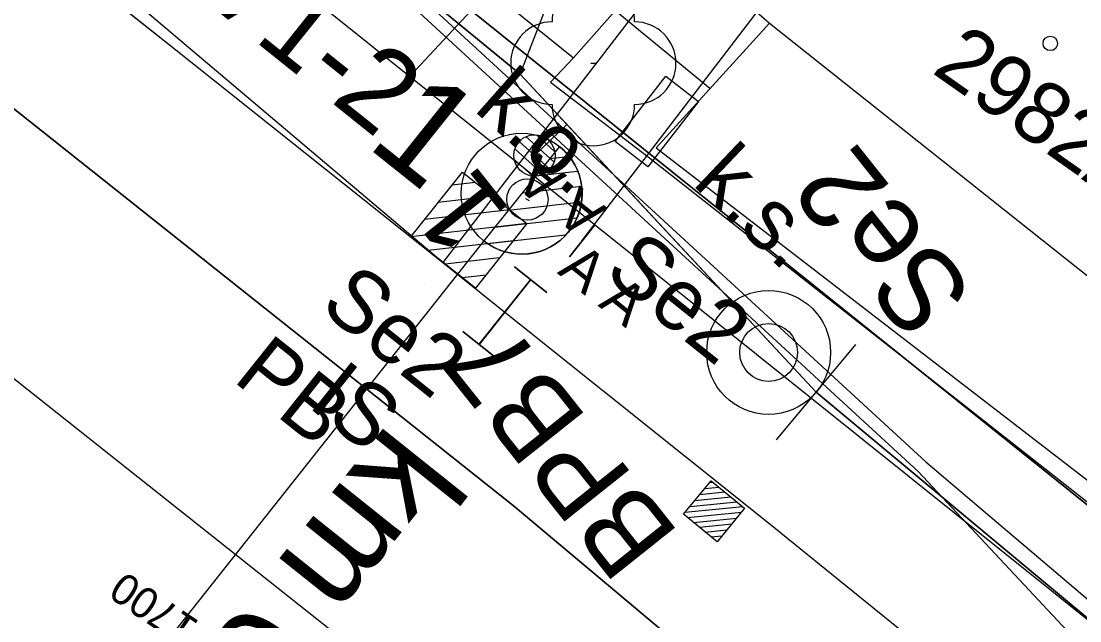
# Model space of a CAD drawing. Extents: x -620624 to -619936, y -1122925 to -1122325.
# Drawn here: x -620240.42 to -620214.78, y -1122741.3 to -1122726.78 of the extents above; entities that cross this region are included whole.
import ezdxf

# ---------------------------------------------------------------- set-up
doc = ezdxf.new("R2010")
doc.units = 0
for name, color, linetype in [('060603_ROZVODY_NN', 7, 'Continuous'), ('060604_ROZVODY_SEE', 7, 'Continuous'), ('CETIN', 7, 'Continuous'), ('POPIS KABELOVÉ TRASY', 7, 'Continuous'), ('PS 06-14-01_trasa_sdělovací_nové', 7, 'Continuous'), ('SEE', 7, 'Continuous'), ('SSZT', 7, 'Continuous'), ('SSZT-DK', 7, 'Continuous'), ('SSZT-TK', 7, 'Continuous'), ('Vrstva 1', 7, 'Continuous'), ('Vrstva 16', 7, 'Continuous'), ('Vrstva 2', 7, 'Continuous'), ('Vrstva 27', 7, 'Continuous'), ('Vrstva 3', 7, 'Continuous'), ('Vrstva 36', 7, 'Continuous'), ('Vrstva 50', 7, 'Continuous'), ('Vrstva 53', 7, 'Continuous'), ('Vrstva 55', 7, 'Continuous'), ('Vrstva 57', 7, 'Continuous'), ('Vrstva 6', 7, 'Continuous'), ('Vrstva 62', 7, 'Continuous'), ('ČD-T', 7, 'Continuous')]:
    doc.layers.add(name, color=color, linetype=linetype)

msp = doc.modelspace()

# ---------------------------------------------------------------- linework, layer by layer
at = {"layer": '060603_ROZVODY_NN'}
msp.add_lwpolyline([(-620240.174, -1122718.342), (-620228.339, -1122728.069), (-620221.166, -1122735.76), (-620213.633, -1122742.038), (-620205.954, -1122748.188), (-620177.512, -1122774.524), (-620185.522, -1122781.049), (-620181.59, -1122785.57), (-620173.131, -1122796.401), (-620158.909, -1122820.61), (-620151.64, -1122838.53), (-620148.846, -1122845.743), (-620146.967, -1122851.788), (-620142.651, -1122873.562), (-620132.315, -1122871.722), (-620130.544, -1122883.681), (-620130.195, -1122888.406), (-620130.037, -1122888.394)], dxfattribs=at)
at = {"layer": '060604_ROZVODY_SEE'}
msp.add_lwpolyline([(-620176.843, -1122775.143), (-620205.954, -1122748.188), (-620213.633, -1122742.038), (-620221.166, -1122735.76), (-620228.339, -1122728.069), (-620234.256, -1122723.205), (-620240.174, -1122718.342), (-620248.298, -1122711.665), (-620253.571, -1122707.331), (-620257.271, -1122704.364), (-620247.325, -1122692.032), (-620244.518, -1122694.296)], dxfattribs=at)
at = {"layer": 'CETIN'}
for points in [[(-620281.95, -1122736.09), (-620279.78, -1122731.91), (-620278.12, -1122730.04), (-620275.23, -1122726.8), (-620267.96, -1122716.51), (-620253.8, -1122706.08), (-620234.3, -1122721.82), (-620227.04, -1122727.67)], [(-620227.04, -1122727.67), (-620224.61, -1122724.91)], [(-620227.04, -1122727.67), (-620227.6, -1122728.26), (-620225.24, -1122730.07), (-620192.39, -1122755.87), (-620182.03, -1122766.47), (-620178.55, -1122770.03), (-620178.11, -1122770.48), (-620148.97, -1122814.05), (-620141.74, -1122827.78), (-620093.42, -1122851.53), (-620088.91, -1122854.99)]]:
    msp.add_lwpolyline(points, dxfattribs=at)
at = {"layer": 'POPIS KABELOVÉ TRASY'}
msp.add_lwpolyline([(-620228.339, -1122728.069), (-620218.049, -1122701.604), (-620224.371, -1122697.311)], dxfattribs=at)
at = {"layer": 'PS 06-14-01_trasa_sdělovací_nové'}
msp.add_lwpolyline([(-620232.134, -1122718.841), (-620235.045, -1122722.562), (-620243.025, -1122715.998), (-620248.321, -1122722.765), (-620228.504, -1122738.508), (-620211.634, -1122752.654), (-620198.933, -1122763.626), (-620190.05, -1122772.28), (-620190.33, -1122775.52), (-620181.59, -1122785.57), (-620173.131, -1122796.401), (-620158.909, -1122820.61), (-620151.64, -1122838.53), (-620148.846, -1122845.743), (-620147.082, -1122852.395), (-620142.651, -1122873.562), (-620132.315, -1122871.722), (-620130.544, -1122883.681), (-620129.885, -1122892.603), (-620129.304, -1122896.718), (-620128.979, -1122906.776)], dxfattribs=at)
at = {"layer": 'SEE'}
msp.add_lwpolyline([(-620257.826, -1122706.644), (-620244.955, -1122716.952), (-620221.313, -1122735.887), (-620205.954, -1122748.188), (-620187.818, -1122764.98), (-620176.843, -1122775.143)], dxfattribs=at)
at = {"layer": 'SSZT'}
msp.add_lwpolyline([(-620131.713, -1122887.843), (-620132.103, -1122876.02), (-620140.705, -1122844.513), (-620144.18, -1122829.908), (-620149.89, -1122817.622), (-620160.216, -1122801.593), (-620175.654, -1122778.856), (-620179.825, -1122771.902), (-620189.291, -1122760.708), (-620207.424, -1122744.252), (-620237.066, -1122720.469), (-620255.602, -1122705.516), (-620251.355, -1122700.201)], dxfattribs=at)
at = {"layer": 'SSZT-DK'}
msp.add_lwpolyline([(-620414.385, -1122636.12), (-620392.309, -1122655.212), (-620359.04, -1122685.798), (-620308.772, -1122717.798), (-620291.405, -1122732.208), (-620277.196, -1122744.115), (-620257.608, -1122720.05), (-620250.251, -1122710.721), (-620233.29, -1122724.26), (-620218.699, -1122737.685), (-620210.438, -1122746.518), (-620193.319, -1122761.993), (-620178.352, -1122775.894), (-620171.184, -1122783.621), (-620164.843, -1122792.284), (-620156.695, -1122803.312), (-620146.306, -1122818.994), (-620117.638, -1122885.131), (-620110.298, -1122902.137)], dxfattribs=at)
at = {"layer": 'SSZT-TK'}
msp.add_line((-620229.519, -1122726.524), (-620231.426, -1122728.569), dxfattribs=at)
msp.add_lwpolyline([(-620251.547, -1122700.3), (-620255.602, -1122705.516), (-620237.066, -1122720.469), (-620207.424, -1122744.252), (-620189.291, -1122760.708), (-620179.825, -1122771.902), (-620175.654, -1122778.856), (-620160.216, -1122801.593), (-620149.89, -1122817.622), (-620144.18, -1122829.908), (-620140.705, -1122844.513), (-620132.103, -1122876.02), (-620131.713, -1122886.934), (-620131.713, -1122887.843), (-620128.502, -1122887.822), (-620131.713, -1122887.843), (-620131.713, -1122904.919)], dxfattribs=at)
at = {"layer": 'Vrstva 1'}
for p, q in [((-620227.989, -1122730.033), (-620227.205, -1122729.285)), ((-620227.205, -1122729.285), (-620221.166, -1122735.76))]:
    msp.add_line(p, q, dxfattribs=at)
for points in [[(-620348.688, -1122637.935), (-620341.5, -1122642.47), (-620339.854, -1122643.512), (-620333.156, -1122647.798), (-620327.653, -1122651.408), (-620321.139, -1122655.817), (-620314.146, -1122660.717), (-620307.245, -1122665.745), (-620300.366, -1122670.953), (-620293.063, -1122676.601), (-620287.47, -1122681.018), (-620281.24, -1122686.066), (-620276.174, -1122690.251), (-620272.417, -1122693.451), (-620267.757, -1122697.544), (-620266.519, -1122698.689), (-620262.242, -1122702.65), (-620256.103, -1122708.562), (-620249.907, -1122714.621), (-620245.657, -1122718.815), (-620238.557, -1122725.547), (-620230.199, -1122732.623), (-620229.854, -1122732.906)], [(-620287.988, -1122686.712), (-620281.909, -1122691.52), (-620277.852, -1122694.735), (-620274.362, -1122697.517), (-620269.944, -1122701.034), (-620263.761, -1122705.928), (-620255.894, -1122712.191), (-620251.107, -1122715.999), (-620247.589, -1122718.79), (-620245.37, -1122720.556), (-620245.065, -1122720.798), (-620243.16, -1122722.318), (-620236.673, -1122727.474), (-620229.854, -1122732.906), (-620228.705, -1122733.823), (-620228.351, -1122734.106), (-620222.324, -1122738.923)], [(-620287.988, -1122686.712), (-620281.909, -1122691.52), (-620277.852, -1122694.735), (-620274.362, -1122697.517), (-620269.944, -1122701.034), (-620263.761, -1122705.928), (-620255.894, -1122712.191), (-620251.107, -1122715.999), (-620247.589, -1122718.79), (-620245.37, -1122720.556), (-620245.065, -1122720.798), (-620243.16, -1122722.318), (-620236.673, -1122727.474), (-620229.854, -1122732.906), (-620228.705, -1122733.823), (-620228.351, -1122734.106), (-620222.324, -1122738.923), (-620215.936, -1122744.099)], [(-620235.055, -1122722.549), (-620228.339, -1122728.069), (-620227.205, -1122729.285)], [(-620173.839, -1122795.494), (-620176.67, -1122791.87), (-620181.59, -1122785.57), (-620185.43, -1122781.13), (-620190.33, -1122775.52), (-620190.05, -1122772.28), (-620198.933, -1122763.626), (-620211.634, -1122752.654), (-620228.504, -1122738.508), (-620248.321, -1122722.765)]]:
    msp.add_lwpolyline(points, dxfattribs=at)
at = {"layer": 'Vrstva 16'}
msp.add_lwpolyline([(-620223.739, -1122728.414), (-620230.921, -1122722.506), (-620236.041, -1122718.293), (-620237.607, -1122717.084), (-620236.205, -1122715.408), (-620251.701, -1122703.411), (-620251.364, -1122702.889), (-620249.497, -1122700.283), (-620232.51, -1122713.28), (-620235.025, -1122716.425), (-620234.751, -1122716.645), (-620225.938, -1122723.731)], dxfattribs=at)
at = {"layer": 'Vrstva 2'}
for p, q in [((-620227.517, -1122730.191), (-620228.194, -1122729.578)), ((-620227.5, -1122729.937), (-620227.942, -1122729.537)), ((-620227.384, -1122729.816), (-620229.212, -1122732.102)), ((-620227.786, -1122730.488), (-620228.462, -1122729.875)), ((-620227.619, -1122730.369), (-620228.359, -1122729.699)), ((-620228.037, -1122730.529), (-620228.478, -1122730.13)), ((-620227.623, -1122730.111), (-620227.149, -1122730.058)), ((-620227.954, -1122730.526), (-620226.945, -1122730.414)), ((-620228.285, -1122730.94), (-620226.85, -1122730.78)), ((-620228.618, -1122731.354), (-620226.852, -1122731.157)), ((-620228.949, -1122731.768), (-620226.963, -1122731.547)), ((-620229.121, -1122732.165), (-620227.234, -1122731.955)), ((-620229.212, -1122732.102), (-620229.854, -1122732.906)), ((-620229.854, -1122732.906), (-620238.907, -1122744.323)), ((-620222.125, -1122736.913), (-620220.207, -1122734.607)), ((-620223.868, -1122738.095), (-620223.523, -1122738.061)), ((-620223.75, -1122737.951), (-620223.667, -1122737.943)), ((-620224.103, -1122738.382), (-620223.236, -1122738.296)), ((-620223.986, -1122738.238), (-620223.38, -1122738.178)), ((-620224.338, -1122738.669), (-620222.949, -1122738.531)), ((-620224.221, -1122738.526), (-620223.092, -1122738.413)), ((-620224.283, -1122738.796), (-620222.978, -1122738.666)), ((-620224.139, -1122738.913), (-620223.096, -1122738.809)), ((-620223.996, -1122739.031), (-620223.214, -1122738.953)), ((-620223.852, -1122739.148), (-620223.331, -1122739.096)), ((-620223.708, -1122739.266), (-620223.449, -1122739.24))]:
    msp.add_line(p, q, dxfattribs=at)
for points in [[(-620249.907, -1122714.621), (-620245.657, -1122718.815), (-620238.557, -1122725.547), (-620230.199, -1122732.623), (-620229.854, -1122732.906)], [(-620251.107, -1122715.999), (-620247.589, -1122718.79), (-620245.37, -1122720.556), (-620245.065, -1122720.798), (-620243.16, -1122722.318), (-620238.765, -1122725.812), (-620236.673, -1122727.474), (-620229.854, -1122732.906)]]:
    msp.add_lwpolyline(points, dxfattribs=at)
msp.add_lwpolyline([(-620223.713, -1122737.905), (-620222.9, -1122738.571), (-620223.566, -1122739.383), (-620224.378, -1122738.718)], close=True, dxfattribs=at)
msp.add_lwpolyline([(-620223.713, -1122737.905), (-620222.9, -1122738.571), (-620223.566, -1122739.383), (-620224.378, -1122738.718)], close=True, dxfattribs=at)
for centre, radius in [((-620228.298, -1122730.959), 1.464), ((-620227.989, -1122730.033), 0.5), ((-620222.319, -1122734.801), 1.5), ((-620222.319, -1122734.801), 0.7)]:
    msp.add_circle(centre, radius, dxfattribs=at)
msp.add_arc((-620228.298, -1122730.959), 1.463, 231.386, 51.3468, dxfattribs=at)
at = {"layer": 'Vrstva 27'}
msp.add_line((-620228.203, -1122731.073), (-620228.117, -1122731.125), dxfattribs=at)
msp.add_circle((-620228.16, -1122731.099), 0.5, dxfattribs=at)
at = {"layer": 'Vrstva 3'}
for p, q in [((-620230.199, -1122732.623), (-620210.91, -1122707.563)), ((-620229.413, -1122730.691), (-620229.988, -1122730.756)), ((-620228.999, -1122731.022), (-620230.319, -1122731.17)), ((-620228.584, -1122731.353), (-620230.65, -1122731.585)), ((-620228.17, -1122731.684), (-620230.981, -1122731.999)), ((-620228.5, -1122732.098), (-620230.566, -1122732.33)), ((-620228.832, -1122732.513), (-620230.151, -1122732.661)), ((-620228.472, -1122732.73), (-620227.69, -1122733.353)), ((-620227.69, -1122733.354), (-620228.471, -1122732.73)), ((-620229.162, -1122732.927), (-620229.737, -1122732.992)), ((-620228.081, -1122733.041), (-620229.329, -1122734.605)), ((-620229.329, -1122734.604), (-620228.081, -1122733.042)), ((-620228.939, -1122734.916), (-620229.72, -1122734.292)), ((-620229.72, -1122734.293), (-620228.938, -1122734.916))]:
    msp.add_line(p, q, dxfattribs=at)
msp.add_lwpolyline([(-620229.417, -1122733.247), (-620230.981, -1122731.999), (-620229.733, -1122730.436), (-620228.17, -1122731.684)], close=True, dxfattribs=at)
at = {"layer": 'Vrstva 36'}
msp.add_lwpolyline([(-620225.246, -1122730.307), (-620226.036, -1122729.694), (-620224.81, -1122728.113), (-620224.02, -1122728.726), (-620225.246, -1122730.307)], dxfattribs=at)
at = {"layer": 'Vrstva 50'}
msp.add_line((-620226.624, -1122727.801), (-620226.482, -1122727.801), dxfattribs=at)
for centre, start, end in [((-620226.564, -1122726.799), 0, 180), ((-620227.564, -1122727.799), 90, 270), ((-620225.564, -1122727.799), 270, 90), ((-620226.564, -1122728.799), 180, 0)]:
    msp.add_arc(centre, 1, start, end, dxfattribs=at)
at = {"layer": 'Vrstva 53'}
for p, q in [((-620223.68, -1122725.62), (-620222.3, -1122726.83)), ((-620222.3, -1122726.83), (-620225.04, -1122729.85)), ((-620225.04, -1122729.85), (-620205.48, -1122744.93)), ((-620246.12, -1122731.05), (-620221.1, -1122750.9))]:
    msp.add_line(p, q, dxfattribs=at)
at = {"layer": 'Vrstva 55'}
for p, q in [((-620223.68, -1122725.62), (-620222.3, -1122726.83)), ((-620222.3, -1122726.83), (-620225.04, -1122729.85)), ((-620222.3, -1122726.83), (-620212.02, -1122735)), ((-620225.04, -1122729.85), (-620205.48, -1122744.93)), ((-620246.12, -1122731.05), (-620221.1, -1122750.9))]:
    msp.add_line(p, q, dxfattribs=at)
at = {"layer": 'Vrstva 57'}
msp.add_circle((-620215.5, -1122727.32), 0.175, dxfattribs=at)
at = {"layer": 'Vrstva 6'}
for p, q in [((-620226.831, -1122732.095), (-620209.385, -1122709.263)), ((-620227.143, -1122732.486), (-620226.519, -1122731.704)), ((-620226.519, -1122731.704), (-620227.143, -1122732.486))]:
    msp.add_line(p, q, dxfattribs=at)
at = {"layer": 'Vrstva 62'}
for p, q in [((-620229.734, -1122732.072), (-620229.734, -1122732.072)), ((-620229.418, -1122732.34), (-620229.418, -1122732.34)), ((-620230.659, -1122733.166), (-620230.659, -1122733.166)), ((-620230.307, -1122733.444), (-620230.307, -1122733.444)), ((-620228.274, -1122733.27), (-620228.274, -1122733.27)), ((-620229.185, -1122734.341), (-620229.185, -1122734.341))]:
    msp.add_line(p, q, dxfattribs=at)
at = {"layer": 'ČD-T'}
msp.add_lwpolyline([(-620414.216, -1122635.87), (-620392.122, -1122654.977), (-620358.852, -1122685.564), (-620308.585, -1122717.564), (-620291.218, -1122731.973), (-620279.983, -1122741.462), (-620260.482, -1122717.473), (-620252.938, -1122708.192), (-620233.103, -1122724.025), (-620218.511, -1122737.45), (-620206.638, -1122747.527), (-620193.132, -1122761.758), (-620178.165, -1122775.66), (-620170.996, -1122783.386), (-620164.655, -1122792.049), (-620156.507, -1122803.078), (-620146.119, -1122818.76), (-620117.451, -1122884.896), (-620110.11, -1122901.903)], dxfattribs=at)

# ---------------------------------------------------------------- texts
at = {"layer": 'POPIS KABELOVÉ TRASY'}
msp.add_text('PROT. HL. 1700', height=0.75, rotation=145.8181, dxfattribs=at).set_placement((-620231.789, -1122744.241))
at = {"layer": 'Vrstva 2'}
for s, rotation, p in [('1', 321.3669, (-620232.091, -1122729.792)), ('km 63,482', 231.3669, (-620231.518, -1122736.471))]:
    msp.add_text(s, height=2.5, rotation=rotation, dxfattribs=at).set_placement(p)
at = {"layer": 'Vrstva 27'}
for s, height, rotation, p in [('V1-2', 2, 321.298, (-620236.203, -1122726.112)), ('k.o.', 1.5, 318.5205, (-620229.486, -1122728.932))]:
    msp.add_text(s, height=height, rotation=rotation, dxfattribs=at).set_placement(p)
at = {"layer": 'Vrstva 3'}
for s, height, rotation, p in [('Se2', 2, 128.542, (-620217.295, -1122733.378)), ('1', 2, 128.542, (-620228.524, -1122731.405)), ('PB', 1.5, 321.4071, (-620235.318, -1122735.477)), ('BPB7', 2, 128.542, (-620224.449, -1122739.213)), ('IS', 1.5, 321.4071, (-620233.508, -1122736.093))]:
    msp.add_text(s, height=height, rotation=rotation, dxfattribs=at).set_placement(p)
at = {"layer": 'Vrstva 36'}
msp.add_text('k.s.', height=1.5, rotation=316.4623, dxfattribs=at).set_placement((-620224.191, -1122730.727))
at = {"layer": 'Vrstva 57'}
msp.add_text('2982/2', height=1.5, rotation=324.9, dxfattribs=at).set_placement((-620218.399, -1122728.013))
at = {"layer": 'Vrstva 6'}
for s, height, rotation, p in [('A A ', 1, 141.3669, (-620226.207, -1122731.314)), ('Se2', 1.5, 321.3669, (-620226.344, -1122732.935)), ('A A ', 1, 321.3669, (-620227.455, -1122732.876)), ('Se2', 1.5, 321.3669, (-620233.225, -1122733.741))]:
    msp.add_text(s, height=height, rotation=rotation, dxfattribs=at).set_placement(p)

doc.saveas('drawing.dxf')
